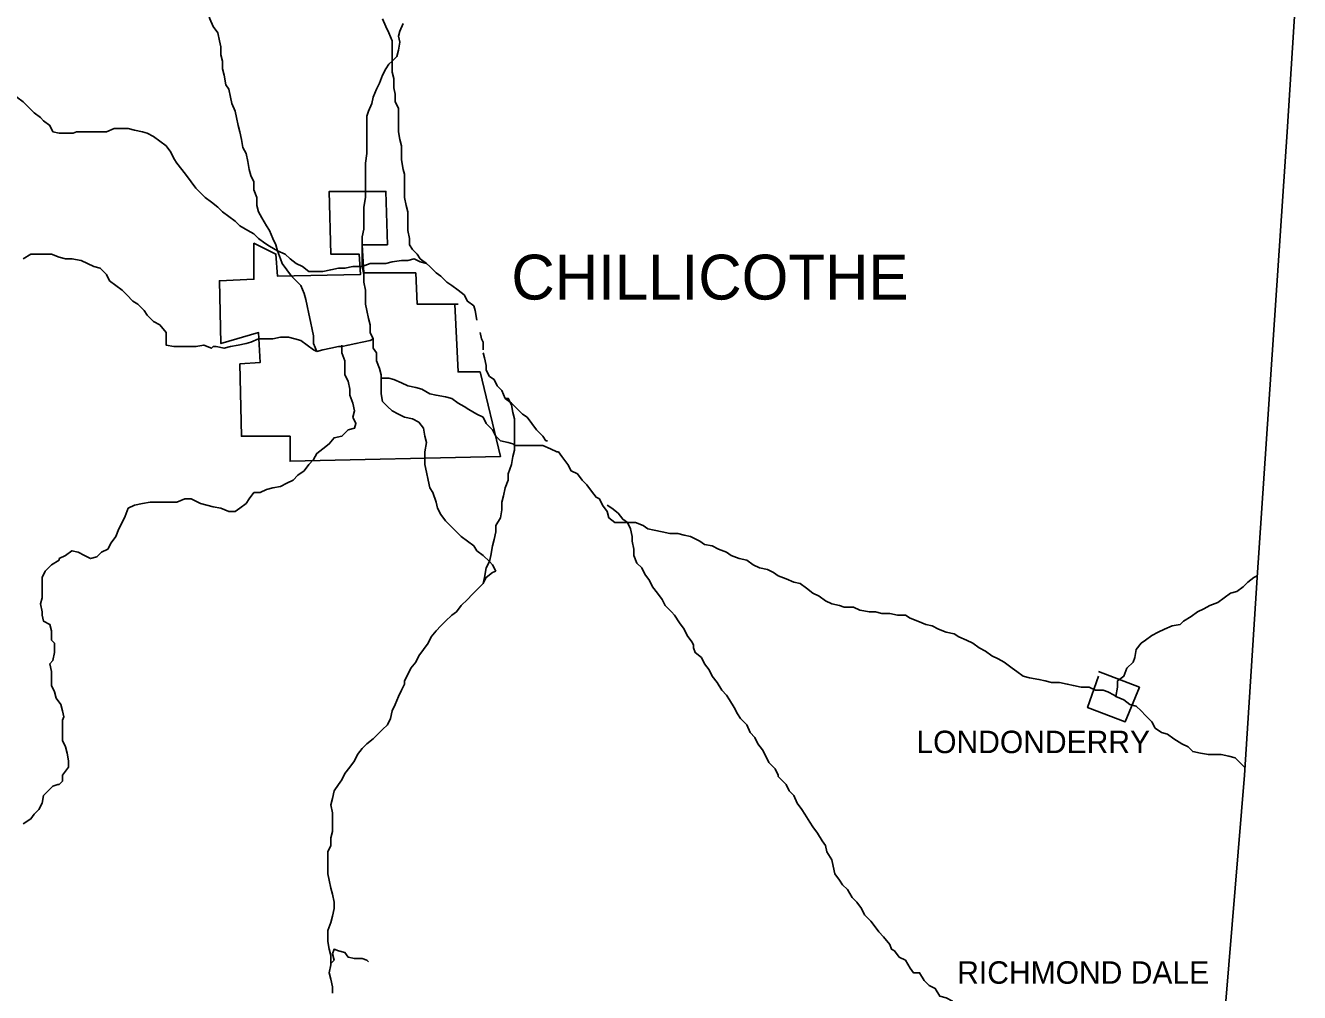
# Model space of a CAD drawing. Extents: x 0 to 34, y 0 to 22.
# Drawn here: x 5.85 to 6.957, y 18.617 to 19.457 of the extents above; entities that cross this region are included whole.
import ezdxf

# ---------------------------------------------------------------- set-up
doc = ezdxf.new("R2010")
doc.units = 0
doc.layers.add('Default', color=7, linetype='Continuous')

msp = doc.modelspace()

# ---------------------------------------------------------------- linework, layer by layer
at = {"layer": 'Default'}
for p, q in [((6.2462, 19.1847), (6.2449, 19.1901)), ((6.2462, 19.1847), (6.2476, 19.1819)), ((6.2476, 19.1751), (6.2476, 19.1819)), ((6.2489, 19.1683), (6.2476, 19.1724)), ((6.2489, 19.1683), (6.2503, 19.1615)), ((6.2503, 19.1574), (6.2503, 19.1615)), ((6.253, 19.152), (6.2503, 19.1574)), ((6.2503, 19.1574), (6.253, 19.152)), ((6.2571, 19.1492), (6.253, 19.152)), ((6.2571, 19.1492), (6.2599, 19.1438)), ((6.2599, 19.1438), (6.2639, 19.1397)), ((6.2667, 19.1329), (6.2639, 19.1397))]:
    msp.add_line(p, q, dxfattribs=at)
for points in [[(6.9566, 19.5337), (6.9457, 19.3646), (6.9197, 18.9774), (6.9088, 18.8056), (6.8925, 18.6093)], [(6.024, 19.4055), (6.0226, 19.4137), (6.0213, 19.4192), (6.0213, 19.426), (6.0199, 19.4315), (6.0199, 19.4383), (6.0185, 19.4437), (6.0172, 19.4505), (6.0131, 19.456), (6.0103, 19.4628), (6.009, 19.4669), (6.009, 19.4669)], [(6.1685, 19.426), (6.1685, 19.4315), (6.1685, 19.4383), (6.1685, 19.4437), (6.1658, 19.4505), (6.1631, 19.456), (6.1603, 19.4628)], [(6.1685, 19.426), (6.1726, 19.4301), (6.174, 19.4355), (6.1753, 19.4424), (6.174, 19.4478), (6.1753, 19.4519), (6.178, 19.4587)], [(6.1426, 19.2474), (6.1426, 19.2542), (6.1426, 19.261), (6.1426, 19.2665), (6.1426, 19.2733), (6.144, 19.2801), (6.144, 19.2869), (6.144, 19.2937), (6.144, 19.2992), (6.1453, 19.3074), (6.1453, 19.3128), (6.1453, 19.3197), (6.1453, 19.3265), (6.1453, 19.3319), (6.1453, 19.3374), (6.1467, 19.3456), (6.1467, 19.351), (6.1467, 19.3578), (6.1467, 19.3646), (6.1467, 19.3715), (6.1467, 19.3783), (6.1481, 19.3824), (6.1508, 19.3892), (6.1521, 19.3946), (6.1549, 19.4015), (6.1576, 19.4069), (6.1603, 19.4137), (6.1631, 19.4192), (6.1658, 19.4233), (6.1685, 19.426)], [(6.1821, 19.2951), (6.1808, 19.3006), (6.1794, 19.3074), (6.1794, 19.3142), (6.1794, 19.321), (6.1794, 19.3278), (6.178, 19.3319), (6.1767, 19.3401), (6.1767, 19.3456), (6.1767, 19.3524), (6.1753, 19.3578), (6.174, 19.3646), (6.174, 19.3715), (6.174, 19.3783), (6.174, 19.3851), (6.1712, 19.3906), (6.1712, 19.3974), (6.1699, 19.4028), (6.1699, 19.411), (6.1685, 19.4165), (6.1685, 19.4219), (6.1685, 19.426)], [(5.7922, 19.4165), (5.7977, 19.4151), (5.8045, 19.4137), (5.8113, 19.4137), (5.8167, 19.411), (5.8236, 19.4083), (5.829, 19.4055), (5.8331, 19.4028), (5.8386, 19.4001), (5.8426, 19.3946), (5.8481, 19.3906), (5.8522, 19.3865), (5.8576, 19.381), (5.8631, 19.3769), (5.8658, 19.3742), (5.8658, 19.3742)], [(6.0526, 19.2951), (6.0512, 19.3006), (6.0512, 19.3074), (6.0485, 19.3142), (6.0485, 19.321), (6.0458, 19.3265), (6.0444, 19.3319), (6.0431, 19.3387), (6.0417, 19.3456), (6.039, 19.351), (6.0376, 19.3578), (6.0363, 19.3646), (6.0349, 19.3701), (6.0335, 19.3769), (6.0322, 19.3824), (6.0294, 19.3892), (6.0281, 19.3946), (6.0267, 19.4015), (6.024, 19.4055)], [(5.8658, 19.3742), (5.8713, 19.3701), (5.874, 19.3646), (5.8795, 19.3633), (5.8876, 19.3633), (5.8917, 19.3633), (5.8945, 19.3646)], [(5.8945, 19.3646), (5.9013, 19.3646), (5.9067, 19.3646), (5.9149, 19.3646), (5.9204, 19.3646), (5.9272, 19.3674), (5.9326, 19.3674), (5.9394, 19.3674), (5.9449, 19.366), (5.9517, 19.3646), (5.9558, 19.3633), (5.9613, 19.3606), (5.9667, 19.3565), (5.9722, 19.3524), (5.9763, 19.3469), (5.979, 19.3415), (5.9817, 19.3374), (5.9858, 19.3319), (5.9899, 19.3265), (5.994, 19.321), (5.9981, 19.3156), (6.0022, 19.3115), (6.0063, 19.3074), (6.0117, 19.3033), (6.0172, 19.2992), (6.0213, 19.2951), (6.0267, 19.291), (6.0322, 19.2869), (6.0363, 19.2828), (6.0431, 19.2788), (6.0485, 19.276), (6.0526, 19.2719), (6.0581, 19.2678), (6.0622, 19.2651), (6.069, 19.261), (6.069, 19.261), (6.069, 19.261)], [(6.2258, 19.2147), (6.223, 19.2147), (6.2258, 19.156), (6.2449, 19.156), (6.2626, 19.0824), (6.0799, 19.0783), (6.0799, 19.1001), (6.0376, 19.1001), (6.0363, 19.1629), (6.054, 19.1642), (6.0526, 19.1901), (6.0199, 19.1806), (6.0185, 19.2351), (6.0485, 19.2365), (6.0485, 19.2678), (6.0676, 19.2583), (6.069, 19.2392), (6.1412, 19.2406), (6.1399, 19.2583), (6.1153, 19.2583), (6.114, 19.3128), (6.1631, 19.3128), (6.1644, 19.2665), (6.1426, 19.2665), (6.144, 19.2419), (6.189, 19.2419), (6.1903, 19.2147), (6.223, 19.2147)], [(6.069, 19.261), (6.0676, 19.2665), (6.0649, 19.2719), (6.0622, 19.2788), (6.0594, 19.2828), (6.0553, 19.2897), (6.0526, 19.2951), (6.0526, 19.2951), (6.0526, 19.2951)], [(6.1985, 19.2501), (6.193, 19.2542), (6.1903, 19.2583), (6.1862, 19.2624), (6.1835, 19.2665), (6.1835, 19.2719), (6.1821, 19.2788), (6.1821, 19.2856), (6.1821, 19.291), (6.1821, 19.2951)], [(5.8481, 19.2542), (5.8549, 19.2583), (5.8604, 19.2583), (5.8658, 19.2583), (5.8726, 19.2583), (5.8795, 19.2556), (5.8849, 19.2542), (5.8904, 19.2542), (5.8985, 19.2528), (5.904, 19.2501), (5.9095, 19.2474), (5.9149, 19.246), (5.9204, 19.2406), (5.9231, 19.2351), (5.9285, 19.231), (5.934, 19.2269), (5.9381, 19.2229), (5.9435, 19.2174), (5.9476, 19.2147), (5.9531, 19.2092), (5.9558, 19.2051), (5.9613, 19.1997), (5.9667, 19.1969), (5.9722, 19.1901), (5.9722, 19.1847), (5.9722, 19.1792), (5.979, 19.1779), (5.9858, 19.1779), (5.9926, 19.1779), (5.9981, 19.1779), (6.0049, 19.1792), (6.0117, 19.1765), (6.0131, 19.1779), (6.0158, 19.1779)], [(6.1031, 19.1738), (6.1003, 19.1806), (6.1003, 19.1874), (6.099, 19.1929), (6.0976, 19.1997), (6.0962, 19.2065), (6.0949, 19.2133), (6.0935, 19.2188), (6.0922, 19.2242), (6.0894, 19.231), (6.0853, 19.2351), (6.0812, 19.2392), (6.0772, 19.2447), (6.0731, 19.2501), (6.0717, 19.2542), (6.069, 19.261)], [(6.069, 19.261), (6.0758, 19.2583), (6.0799, 19.2542), (6.0853, 19.2501), (6.0908, 19.2474), (6.0962, 19.2433), (6.1031, 19.2433), (6.1085, 19.2433), (6.1153, 19.2447), (6.1221, 19.246), (6.1276, 19.246), (6.1344, 19.2474), (6.1412, 19.2474), (6.1426, 19.2474)], [(6.1426, 19.2474), (6.1494, 19.2501), (6.1562, 19.2501), (6.1631, 19.2501), (6.1685, 19.2515), (6.1767, 19.2528), (6.1821, 19.2528), (6.1876, 19.2542), (6.193, 19.2515), (6.1985, 19.2501), (6.1985, 19.2501)], [(6.1521, 19.1847), (6.1494, 19.1901), (6.1494, 19.1969), (6.1481, 19.2024), (6.1467, 19.2092), (6.1453, 19.2147), (6.1453, 19.2215), (6.1453, 19.2269), (6.144, 19.2338), (6.144, 19.2406), (6.1426, 19.2474), (6.1426, 19.2474)], [(6.2421, 19.201), (6.2408, 19.2092), (6.2394, 19.2133), (6.2339, 19.2174), (6.2312, 19.2229), (6.2258, 19.2269), (6.2203, 19.231), (6.2162, 19.2338), (6.2108, 19.2392), (6.2067, 19.2419), (6.2012, 19.2474), (6.1985, 19.2501)], [(6.1985, 19.2501), (6.2012, 19.2474), (6.2067, 19.2419), (6.2108, 19.2392), (6.2162, 19.2338), (6.2203, 19.231), (6.2258, 19.2269), (6.2312, 19.2229), (6.2339, 19.2174), (6.2394, 19.2133), (6.2408, 19.2092), (6.2421, 19.201)], [(6.0158, 19.1779), (6.0226, 19.1765), (6.0281, 19.1779), (6.0349, 19.1792), (6.0417, 19.1806), (6.0458, 19.1819), (6.0526, 19.1847), (6.0581, 19.1847), (6.0649, 19.1847), (6.0717, 19.186), (6.0785, 19.186), (6.084, 19.1847), (6.0894, 19.1833), (6.0949, 19.1792), (6.1003, 19.1751), (6.1031, 19.1738)], [(5.8795, 18.9938), (5.8849, 18.9965), (5.8904, 19.0006), (5.8958, 18.9992), (5.9013, 18.9965), (5.9067, 18.9938), (5.9122, 18.9952), (5.9163, 18.9992), (5.9217, 19.002), (5.9245, 19.0074), (5.9285, 19.0129), (5.9313, 19.0197), (5.934, 19.0252), (5.9367, 19.0306), (5.9394, 19.0374), (5.9449, 19.0402), (5.9517, 19.0415), (5.9585, 19.0429), (5.964, 19.0429), (5.9708, 19.0429), (5.9776, 19.0429), (5.9817, 19.0429), (5.9885, 19.0456), (5.994, 19.0456), (6.0022, 19.0415), (6.0076, 19.0402), (6.0131, 19.0388), (6.0199, 19.0374), (6.0267, 19.0347), (6.0322, 19.0347), (6.0363, 19.0374), (6.0417, 19.0415), (6.0444, 19.0456), (6.0485, 19.0511), (6.054, 19.0511), (6.0594, 19.0538), (6.0649, 19.0551), (6.0717, 19.0565), (6.0772, 19.0592), (6.0826, 19.062), (6.0867, 19.0661), (6.0922, 19.0701), (6.0962, 19.0756), (6.1003, 19.0797), (6.1031, 19.0851), (6.1085, 19.0892), (6.114, 19.0933), (6.1181, 19.0988), (6.1249, 19.1001), (6.1303, 19.1056), (6.1358, 19.107), (6.1371, 19.1111), (6.1344, 19.1165), (6.1358, 19.122), (6.1344, 19.1288), (6.1317, 19.1356), (6.1317, 19.141), (6.1303, 19.1479), (6.1276, 19.1533), (6.1276, 19.1601), (6.1276, 19.1656), (6.1249, 19.1724), (6.1249, 19.1779), (6.1249, 19.1779), (6.1249, 19.1792)], [(6.1031, 19.1738), (6.1085, 19.1751), (6.1153, 19.1765), (6.1221, 19.1779), (6.1249, 19.1779)], [(6.1249, 19.1779), (6.1221, 19.1779), (6.1153, 19.1765), (6.1085, 19.1751), (6.1031, 19.1738)], [(6.1249, 19.1779), (6.1303, 19.1792), (6.1371, 19.1806), (6.1426, 19.1819), (6.1494, 19.1833), (6.1521, 19.1847)], [(6.1521, 19.1847), (6.1494, 19.1833), (6.1426, 19.1819), (6.1371, 19.1806), (6.1303, 19.1792), (6.1249, 19.1779)], [(6.1521, 19.1847), (6.1521, 19.1765), (6.1549, 19.1724), (6.1549, 19.1656), (6.1576, 19.1588), (6.159, 19.1533), (6.159, 19.1506)], [(6.159, 19.1506), (6.159, 19.1533), (6.1576, 19.1588), (6.1549, 19.1656), (6.1549, 19.1724), (6.1521, 19.1765), (6.1521, 19.1847)], [(6.159, 19.1506), (6.1658, 19.1506), (6.1699, 19.1492), (6.1767, 19.1465), (6.1821, 19.1438), (6.189, 19.1424), (6.1944, 19.141), (6.2012, 19.137), (6.2067, 19.1356), (6.2149, 19.1342), (6.2203, 19.1329), (6.2258, 19.1288), (6.2312, 19.126), (6.2353, 19.1233), (6.2421, 19.1192), (6.2476, 19.1165), (6.2503, 19.1111), (6.2558, 19.1056), (6.2585, 19.1001), (6.2626, 19.0961), (6.2694, 19.0947), (6.2735, 19.0933), (6.2749, 19.092)], [(6.253, 18.9911), (6.2476, 18.9965), (6.2421, 19.0006), (6.2394, 19.0047), (6.2339, 19.0088), (6.2285, 19.0129), (6.223, 19.0183), (6.219, 19.0224), (6.2149, 19.0265), (6.2108, 19.032), (6.208, 19.0374), (6.2067, 19.0429), (6.204, 19.0511), (6.2012, 19.0551), (6.1999, 19.062), (6.1985, 19.0688), (6.1971, 19.0756), (6.1971, 19.0824), (6.1971, 19.0865), (6.1985, 19.0947), (6.1971, 19.1001), (6.1958, 19.107), (6.1917, 19.1124), (6.1862, 19.1151), (6.1794, 19.1165), (6.174, 19.1192), (6.1685, 19.122), (6.1644, 19.126), (6.1603, 19.1301), (6.159, 19.137), (6.159, 19.1424), (6.159, 19.1492), (6.159, 19.1506), (6.159, 19.1506)], [(6.2749, 19.1083), (6.2749, 19.1151), (6.2735, 19.1206), (6.2721, 19.1274), (6.2694, 19.1329), (6.2667, 19.1329)], [(6.2667, 19.1329), (6.2721, 19.1288), (6.2762, 19.1247), (6.2817, 19.1192), (6.2858, 19.1165), (6.2898, 19.1111), (6.2939, 19.1056), (6.2994, 19.1001), (6.3021, 19.0961), (6.3035, 19.0961)], [(6.2749, 19.092), (6.2749, 19.1001), (6.2749, 19.1056), (6.2749, 19.1083)], [(6.2721, 19.0756), (6.2735, 19.0824), (6.2749, 19.0879), (6.2749, 19.092)], [(6.2749, 19.092), (6.2803, 19.092), (6.2885, 19.092), (6.2939, 19.092), (6.2994, 19.092), (6.3062, 19.0892), (6.3117, 19.0865), (6.313, 19.0865)], [(6.313, 19.0865), (6.3158, 19.0824), (6.3212, 19.0756), (6.3239, 19.0701), (6.3294, 19.0674), (6.3335, 19.062), (6.3376, 19.0579), (6.3417, 19.0524), (6.3457, 19.047), (6.3485, 19.0456)], [(6.313, 19.0865), (6.3158, 19.0824), (6.3212, 19.0756), (6.3239, 19.0701), (6.3294, 19.0674), (6.3335, 19.062), (6.3376, 19.0579), (6.3417, 19.0524), (6.3457, 19.047), (6.3485, 19.0456)], [(6.253, 18.9911), (6.2544, 18.9965), (6.2558, 19.0047), (6.2571, 19.0102), (6.2585, 19.017), (6.2585, 19.0224), (6.2626, 19.0292), (6.2639, 19.0361), (6.2639, 19.0429), (6.2653, 19.0483), (6.2667, 19.0551), (6.2694, 19.062), (6.2694, 19.0674), (6.2721, 19.0756), (6.2721, 19.0756)], [(6.3485, 19.0456), (6.3512, 19.0402), (6.3553, 19.0347), (6.3567, 19.0292), (6.3621, 19.0252), (6.3676, 19.0252), (6.373, 19.0252)], [(6.3553, 19.0402), (6.3594, 19.0374), (6.3648, 19.0333), (6.3689, 19.0279), (6.373, 19.0252), (6.373, 19.0252)], [(6.373, 19.0252), (6.3798, 19.0252), (6.3867, 19.0224), (6.3907, 19.0197), (6.3962, 19.0183), (6.403, 19.017), (6.4098, 19.0156), (6.4166, 19.0156), (6.4221, 19.0142), (6.4276, 19.0129), (6.4357, 19.0088), (6.4398, 19.0061), (6.4466, 19.0047), (6.4521, 19.002), (6.4589, 18.9992), (6.463, 18.9965), (6.4698, 18.9938), (6.4766, 18.9924), (6.4821, 18.9883), (6.4875, 18.9856), (6.4944, 18.9843), (6.4998, 18.9815)], [(6.373, 19.0252), (6.3757, 19.0197), (6.3771, 19.0129), (6.3771, 19.0102), (6.3771, 19.0088)], [(6.3771, 19.0088), (6.3785, 19.002), (6.3785, 18.9965), (6.3812, 18.9897), (6.3853, 18.9856), (6.388, 18.9802), (6.3921, 18.9747), (6.3948, 18.9693), (6.3989, 18.9638), (6.403, 18.9583), (6.4057, 18.9529), (6.4112, 18.9474), (6.4139, 18.9447), (6.418, 18.9379), (6.4221, 18.9324), (6.4248, 18.927), (6.4289, 18.9215), (6.4303, 18.9188), (6.4303, 18.9161)], [(5.8645, 18.9474), (5.8631, 18.9543), (5.8645, 18.9597), (5.8645, 18.9679), (5.8645, 18.9733), (5.8645, 18.9774), (5.8672, 18.9829), (5.8726, 18.9883), (5.8795, 18.9924), (5.8795, 18.9938)], [(6.2476, 18.972), (6.2489, 18.9774), (6.2503, 18.9856), (6.253, 18.9911), (6.253, 18.9911)], [(6.2585, 18.9829), (6.2558, 18.9883), (6.253, 18.9911)], [(6.2476, 18.972), (6.2503, 18.9774), (6.2558, 18.9815), (6.2585, 18.9829)], [(6.4998, 18.9815), (6.5039, 18.9788), (6.5107, 18.9761), (6.5175, 18.9733), (6.523, 18.972), (6.5284, 18.9679), (6.5339, 18.9638), (6.5394, 18.9611), (6.5448, 18.957), (6.5503, 18.9543), (6.5571, 18.9529), (6.5612, 18.9515), (6.5693, 18.9515), (6.5748, 18.9488), (6.583, 18.9474), (6.5884, 18.9474), (6.5939, 18.9461), (6.6007, 18.9461), (6.6075, 18.9447), (6.6143, 18.9447), (6.6184, 18.942), (6.6252, 18.9393), (6.6321, 18.9365), (6.6375, 18.9352), (6.643, 18.9324), (6.6498, 18.9297), (6.6566, 18.9284), (6.6607, 18.9256), (6.6675, 18.9229), (6.673, 18.9202), (6.6784, 18.9161), (6.6839, 18.9134), (6.6893, 18.9093), (6.6948, 18.9065), (6.7002, 18.9038), (6.7071, 18.8984), (6.7111, 18.8956), (6.7166, 18.8915), (6.7221, 18.8902), (6.7302, 18.8888), (6.7357, 18.8874), (6.7411, 18.8861), (6.748, 18.8861), (6.7548, 18.8847), (6.7602, 18.8834), (6.767, 18.882), (6.7739, 18.882), (6.7793, 18.8793), (6.7861, 18.8793), (6.7902, 18.8779), (6.7957, 18.8752), (6.797, 18.8738)], [(6.797, 18.8738), (6.7984, 18.882), (6.7984, 18.8874), (6.8039, 18.8915), (6.8066, 18.8984), (6.812, 18.9038), (6.8134, 18.9079), (6.8148, 18.9147), (6.8189, 18.9202), (6.8229, 18.9229), (6.8284, 18.927), (6.8339, 18.9297), (6.8393, 18.9324), (6.8461, 18.9352), (6.8529, 18.9365), (6.8557, 18.9393), (6.8625, 18.9433), (6.8679, 18.9474), (6.8734, 18.9502), (6.8788, 18.9529), (6.8857, 18.9556), (6.8911, 18.9597), (6.8966, 18.9638), (6.902, 18.9652), (6.9075, 18.9693), (6.9116, 18.9733), (6.917, 18.9774), (6.9197, 18.9788), (6.9197, 18.9788)], [(6.1794, 18.8874), (6.1821, 18.8929), (6.1849, 18.8984), (6.189, 18.9038), (6.1917, 18.9093), (6.1958, 18.9147), (6.1999, 18.9202), (6.2026, 18.9256), (6.2067, 18.9311), (6.2108, 18.9352), (6.2149, 18.9393), (6.2203, 18.9447), (6.2244, 18.9474), (6.2285, 18.9529), (6.2339, 18.9583), (6.238, 18.9624), (6.2421, 18.9665), (6.2476, 18.972), (6.2476, 18.972)], [(6.1794, 18.8874), (6.1821, 18.8929), (6.1849, 18.8984), (6.189, 18.9038), (6.1917, 18.9093), (6.1958, 18.9147), (6.1999, 18.9202), (6.2026, 18.9256), (6.2067, 18.9311), (6.2108, 18.9352), (6.2149, 18.9393), (6.2203, 18.9447), (6.2244, 18.9474), (6.2285, 18.9529), (6.2339, 18.9583), (6.238, 18.9624), (6.2421, 18.9665), (6.2476, 18.972), (6.2476, 18.972)], [(5.8713, 18.9024), (5.874, 18.9052), (5.8754, 18.912), (5.8754, 18.9202), (5.8726, 18.9229), (5.8726, 18.9311), (5.8713, 18.9365), (5.8658, 18.9393), (5.8645, 18.9447), (5.8645, 18.9474), (5.8645, 18.9474)], [(6.4303, 18.9161), (6.4316, 18.912), (6.4371, 18.9079), (6.4398, 18.9024), (6.4439, 18.897), (6.4466, 18.8915), (6.4507, 18.8861), (6.4548, 18.8793), (6.4589, 18.8752), (6.4616, 18.8711), (6.4657, 18.8643), (6.4685, 18.8588), (6.4712, 18.8547), (6.4766, 18.8493), (6.4794, 18.8425), (6.4835, 18.8384), (6.4862, 18.8329), (6.4903, 18.8275), (6.493, 18.822), (6.4957, 18.8166), (6.5012, 18.8111), (6.5039, 18.8056), (6.5039, 18.8043), (6.5053, 18.8029)], [(5.8835, 18.8561), (5.8822, 18.8615), (5.8808, 18.867), (5.8767, 18.8725), (5.8754, 18.8779), (5.8726, 18.8834), (5.8726, 18.8902), (5.8726, 18.8956), (5.8713, 18.9024)], [(6.1167, 18.7675), (6.1167, 18.7729), (6.1153, 18.7797), (6.1167, 18.7852), (6.1181, 18.792), (6.1221, 18.7975), (6.1249, 18.8016), (6.1276, 18.807), (6.1317, 18.8125), (6.1358, 18.8179), (6.1385, 18.8234), (6.1426, 18.8288), (6.1467, 18.8329), (6.1521, 18.837), (6.1562, 18.8411), (6.1603, 18.8452), (6.1644, 18.8493), (6.1671, 18.8547), (6.1685, 18.8615), (6.1712, 18.867), (6.174, 18.8738), (6.1767, 18.8793), (6.1794, 18.8847), (6.1794, 18.8861), (6.1794, 18.8874)], [(6.1167, 18.7675), (6.1167, 18.7729), (6.1153, 18.7797), (6.1167, 18.7852), (6.1181, 18.792), (6.1221, 18.7975), (6.1249, 18.8016), (6.1276, 18.807), (6.1317, 18.8125), (6.1358, 18.8179), (6.1385, 18.8234), (6.1426, 18.8288), (6.1467, 18.8329), (6.1521, 18.837), (6.1562, 18.8411), (6.1603, 18.8452), (6.1644, 18.8493), (6.1671, 18.8547), (6.1685, 18.8615), (6.1712, 18.867), (6.174, 18.8738), (6.1767, 18.8793), (6.1794, 18.8847), (6.1794, 18.8861), (6.1794, 18.8874)], [(6.782, 18.8956), (6.8175, 18.882), (6.8052, 18.852), (6.7725, 18.8643), (6.782, 18.8915)], [(6.797, 18.8738), (6.8039, 18.8711), (6.8093, 18.867), (6.8148, 18.8656), (6.8189, 18.8615), (6.8229, 18.8575), (6.8284, 18.852), (6.8311, 18.8465), (6.8366, 18.8425), (6.842, 18.8411), (6.8475, 18.837), (6.8543, 18.8329), (6.8598, 18.8302), (6.8638, 18.8261), (6.8707, 18.8247), (6.8775, 18.8234), (6.8829, 18.8234), (6.8884, 18.8234), (6.8952, 18.822), (6.9007, 18.8206), (6.9048, 18.8166), (6.9088, 18.8125)], [(5.8795, 18.7975), (5.8822, 18.8002), (5.8822, 18.8056), (5.8876, 18.8125), (5.8876, 18.8179), (5.8863, 18.8247), (5.8849, 18.8302), (5.8822, 18.8356), (5.8822, 18.8411), (5.8822, 18.8465), (5.8822, 18.8534), (5.8835, 18.8561)], [(6.5053, 18.8029), (6.5107, 18.7975), (6.5134, 18.792), (6.5175, 18.7879), (6.5203, 18.7811), (6.5244, 18.7756), (6.5271, 18.7716), (6.5312, 18.7647), (6.5339, 18.7607), (6.538, 18.7552), (6.5421, 18.7484), (6.5448, 18.7443), (6.5462, 18.7388), (6.5503, 18.732), (6.5516, 18.7266), (6.553, 18.7197), (6.5571, 18.7143), (6.5598, 18.7102), (6.5639, 18.7061), (6.568, 18.6993), (6.5721, 18.6952), (6.5762, 18.6898), (6.5789, 18.6843), (6.5843, 18.6788), (6.5871, 18.6748), (6.5912, 18.6693), (6.5953, 18.6652), (6.6007, 18.6584), (6.6021, 18.6543), (6.6048, 18.6529)], [(5.8481, 18.7634), (5.8549, 18.7675), (5.8576, 18.7716), (5.8617, 18.7756), (5.8645, 18.7811), (5.8658, 18.7879), (5.8699, 18.792), (5.874, 18.7961), (5.8781, 18.7975), (5.8795, 18.7975)], [(6.1153, 18.642), (6.1153, 18.6489), (6.114, 18.6543), (6.1126, 18.6611), (6.1126, 18.6652), (6.1126, 18.6707), (6.1153, 18.6775), (6.1167, 18.6829), (6.1181, 18.6898), (6.1181, 18.6952), (6.1167, 18.702), (6.1153, 18.7075), (6.114, 18.7143), (6.1126, 18.7197), (6.1126, 18.7266), (6.1126, 18.732), (6.1126, 18.7388), (6.1153, 18.7443), (6.1153, 18.7511), (6.1167, 18.7566), (6.1167, 18.7647), (6.1167, 18.7675)], [(6.1153, 18.642), (6.1153, 18.6489), (6.114, 18.6543), (6.1126, 18.6611), (6.1126, 18.6652), (6.1126, 18.6707), (6.1153, 18.6775), (6.1167, 18.6829), (6.1181, 18.6898), (6.1181, 18.6952), (6.1167, 18.702), (6.1153, 18.7075), (6.114, 18.7143), (6.1126, 18.7197), (6.1126, 18.7266), (6.1126, 18.732), (6.1126, 18.7388), (6.1153, 18.7443), (6.1153, 18.7511), (6.1167, 18.7566), (6.1167, 18.7647), (6.1167, 18.7675)], [(6.1153, 18.642), (6.1181, 18.6448), (6.1167, 18.6502), (6.1181, 18.6543), (6.1221, 18.6529), (6.1276, 18.6516), (6.1303, 18.6475), (6.1358, 18.6461), (6.1426, 18.6461), (6.1467, 18.6448), (6.1481, 18.6434)], [(6.6048, 18.6529), (6.6089, 18.6475), (6.6143, 18.6448), (6.6184, 18.6379), (6.6212, 18.6339), (6.6266, 18.6339), (6.6307, 18.627), (6.6348, 18.6229), (6.6402, 18.6202), (6.6443, 18.6134), (6.6498, 18.612), (6.6552, 18.6093), (6.6593, 18.6052), (6.6648, 18.6025), (6.6716, 18.5998), (6.6757, 18.597), (6.6825, 18.5957), (6.6866, 18.5902), (6.6866, 18.5889)], [(6.1167, 18.6161), (6.1167, 18.6216), (6.1153, 18.6284), (6.114, 18.6339), (6.1153, 18.6407), (6.1153, 18.6407), (6.1153, 18.642)], [(6.1167, 18.6161), (6.1167, 18.6216), (6.1153, 18.6284), (6.114, 18.6339), (6.1153, 18.6407), (6.1153, 18.6407), (6.1153, 18.642)]]:
    msp.add_lwpolyline(points, dxfattribs=at)

# ---------------------------------------------------------------- texts
for s, height, p in [('CHILLICOTHE', 0.039005, (6.2721, 19.2188)), ('LONDONDERRY', 0.019502, (6.6239, 18.8247)), ('RICHMOND DALE', 0.019502, (6.6593, 18.6243))]:
    msp.add_text(s, height=height, dxfattribs=at).set_placement(p)

doc.saveas('drawing.dxf')
